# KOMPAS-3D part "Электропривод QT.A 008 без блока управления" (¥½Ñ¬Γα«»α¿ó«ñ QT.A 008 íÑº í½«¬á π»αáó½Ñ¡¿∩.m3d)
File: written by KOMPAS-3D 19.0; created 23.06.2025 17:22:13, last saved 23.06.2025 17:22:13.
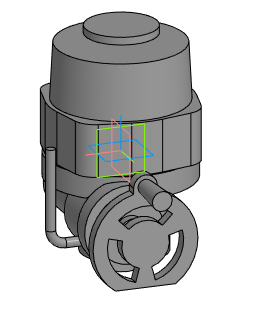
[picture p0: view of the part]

Document properties: Автор: Евгений; Полное имя файла: E:\Dendor Работа Сачек\3D для проектировщиков\3.5 Тип QT.А Электропривод\stp_Электропривод QT.A без блока управления\Электропривод QT.A 008 без блока управления.m3d

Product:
- Part/product: Электропривод QT.A 008 без блока управления

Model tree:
1. Операция без истории:1  (labels: Электропривод QT.A 008 без блока управления)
